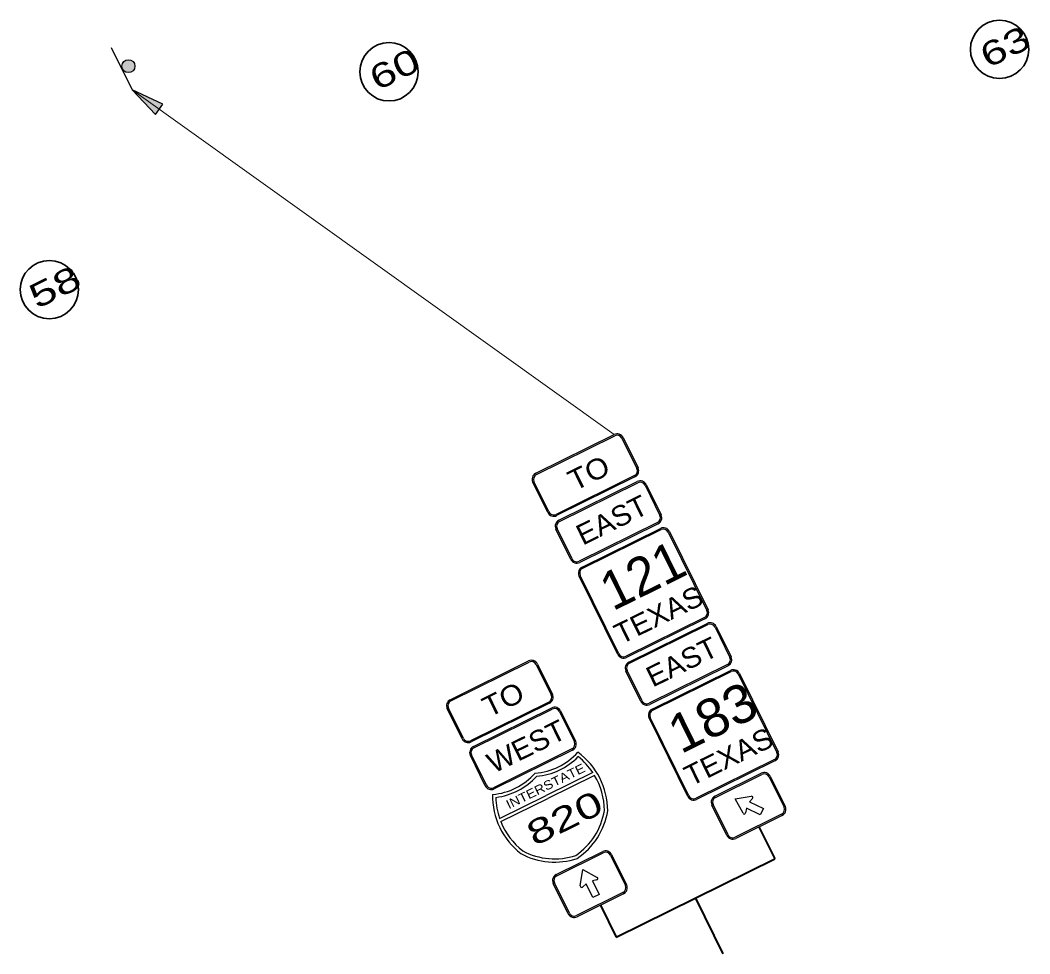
# Model space of a CAD drawing. Extents: x 2356431 to 2371438, y 6972864 to 6982525.
# Drawn here: x 2368952 to 2369535, y 6980523 to 6981061 of the extents above; entities that cross this region are included whole.
import ezdxf
from ezdxf.enums import TextEntityAlignment as Align

# ---------------------------------------------------------------- set-up
doc = ezdxf.new("R2010")
doc.units = 0
doc.header["$LTSCALE"] = 5.6
for name, color, linetype, lineweight in [('1', 7, 'Continuous', 25), ('17', 7, 'Continuous', 35), ('48', 7, 'Continuous', 25)]:
    doc.layers.add(name, color=color, linetype=linetype, lineweight=lineweight)

msp = doc.modelspace()

# ---------------------------------------------------------------- hatches: boundary and pattern name
at = {"layer": '1'}
for points in [[(2369018.675, 6981034.348, 1), (2369011.298, 6981035.483, 1)], [(2369017.082, 6981021.194), (2369030.573, 6981007.07), (2369034.778, 6981012.9)]]:
    msp.add_hatch(color=256, dxfattribs=at).paths.add_polyline_path(points)

# ---------------------------------------------------------------- linework, layer by layer
for p, q in [((2369005.01, 6981045.758), (2369017.082, 6981021.194)), ((2369283.079, 6980627.366), (2369256.179, 6980614.089)), ((2369284.087, 6980625.752), (2369257.018, 6980612.396)), ((2369229.279, 6980600.811), (2369256.179, 6980614.089)), ((2369229.929, 6980599.02), (2369257.018, 6980612.396))]:
    msp.add_line(p, q, dxfattribs=at)
at = {"layer": '1', "lineweight": 13}
msp.add_line((2369017.082, 6981021.194), (2369295.383, 6980822.354), dxfattribs=at)
at = {"layer": '1'}
msp.add_lwpolyline([(2369017.082, 6981021.194), (2369030.573, 6981007.07), (2369034.778, 6981012.9)], close=True, dxfattribs=at)
msp.add_circle((2369014.987, 6981034.916), 3.732, dxfattribs=at)
for centre, radius, start, end in [((2369247.586, 6980663.009), 35.984, 273.44817, 318.29849), ((2369249.694, 6980605.201), 41.954, 0.13097, 53.83335), ((2369247.586, 6980663.009), 37.874, 274.64609, 315.64292), ((2369249.694, 6980605.201), 40.064, 33.57742, 51.44217), ((2369222.557, 6980650.656), 35.984, 274.23709, 319.0874), ((2369222.557, 6980650.656), 37.874, 276.89265, 317.88949), ((2369249.694, 6980605.201), 40.064, 0.34751, 30.85949), ((2369267.159, 6980613.82), 41.954, 178.70222, 232.4046), ((2369267.159, 6980613.82), 40.064, 181.0934, 198.95816), ((2369251.454, 6980611.68), 38.808, 304.10583, 350.75221), ((2369251.454, 6980611.68), 40.698, 303.73968, 350.97558), ((2369267.159, 6980613.82), 40.064, 201.67608, 232.18806), ((2369260.946, 6980616.365), 40.698, 241.55999, 288.79589), ((2369260.946, 6980616.365), 38.808, 241.78337, 288.42975)]:
    msp.add_arc(centre, radius, start, end, dxfattribs=at)
at = {"layer": '17'}
for centre in [(2369517.875, 6981044.608), (2369165.406, 6981031.668), (2368969.308, 6980905.983)]:
    msp.add_circle(centre, 16.828, dxfattribs=at)
at = {"layer": '48'}
for p, q in [((2369250.148, 6980800.029), (2369295.383, 6980822.354)), ((2369250.488, 6980799.34), (2369295.723, 6980821.665)), ((2369299.837, 6980820.27), (2369308.473, 6980802.771)), ((2369300.526, 6980820.61), (2369309.162, 6980803.111)), ((2369307.078, 6980798.657), (2369261.843, 6980776.332)), ((2369307.418, 6980797.968), (2369262.183, 6980775.643)), ((2369263.511, 6980772.953), (2369308.746, 6980795.278)), ((2369257.04, 6980777.387), (2369248.404, 6980794.886)), ((2369257.729, 6980777.727), (2369249.093, 6980795.226)), ((2369263.851, 6980772.264), (2369309.086, 6980794.589)), ((2369313.2, 6980793.194), (2369321.836, 6980775.696)), ((2369313.889, 6980793.534), (2369322.525, 6980776.036)), ((2369270.403, 6980750.312), (2369261.767, 6980767.81)), ((2369271.091, 6980750.652), (2369262.455, 6980768.15)), ((2369320.441, 6980771.581), (2369275.206, 6980749.256)), ((2369320.781, 6980770.893), (2369275.546, 6980748.568)), ((2369276.873, 6980745.877), (2369322.108, 6980768.202)), ((2369277.213, 6980745.189), (2369322.448, 6980767.514)), ((2369326.563, 6980766.119), (2369348.888, 6980720.884)), ((2369327.251, 6980766.458), (2369349.576, 6980721.223)), ((2369297.454, 6980695.5), (2369275.129, 6980740.735)), ((2369298.143, 6980695.839), (2369275.818, 6980741.074)), ((2369347.492, 6980716.769), (2369302.257, 6980694.444)), ((2369347.832, 6980716.081), (2369302.597, 6980693.756)), ((2369303.925, 6980691.065), (2369349.16, 6980713.39)), ((2369304.265, 6980690.377), (2369349.5, 6980712.702)), ((2369353.614, 6980711.306), (2369362.25, 6980693.808)), ((2369354.303, 6980711.646), (2369362.939, 6980694.148)), ((2369200.744, 6980669.396), (2369245.979, 6980691.721)), ((2369201.084, 6980668.708), (2369246.319, 6980691.033)), ((2369250.434, 6980689.638), (2369259.07, 6980672.139)), ((2369251.122, 6980689.977), (2369259.758, 6980672.479)), ((2369310.817, 6980668.424), (2369302.181, 6980685.922)), ((2369311.506, 6980668.764), (2369302.87, 6980686.262)), ((2369360.855, 6980689.694), (2369315.62, 6980667.369)), ((2369361.195, 6980689.005), (2369315.96, 6980666.68)), ((2369317.288, 6980663.99), (2369362.523, 6980686.315)), ((2369317.628, 6980663.301), (2369362.863, 6980685.626)), ((2369367.666, 6980684.571), (2369389.991, 6980639.336)), ((2369366.977, 6980684.231), (2369389.302, 6980638.996)), ((2369257.674, 6980668.025), (2369212.439, 6980645.7)), ((2369258.014, 6980667.336), (2369212.779, 6980645.011)), ((2369207.636, 6980646.755), (2369199, 6980664.254)), ((2369208.325, 6980647.095), (2369199.689, 6980664.593)), ((2369214.107, 6980642.321), (2369259.342, 6980664.646)), ((2369214.447, 6980641.632), (2369259.682, 6980663.957)), ((2369263.796, 6980662.562), (2369272.432, 6980645.064)), ((2369264.485, 6980662.902), (2369273.121, 6980645.403)), ((2369337.869, 6980613.612), (2369315.544, 6980658.847)), ((2369338.557, 6980613.952), (2369316.232, 6980659.187)), ((2369271.037, 6980640.949), (2369225.802, 6980618.624)), ((2369271.377, 6980640.261), (2369226.142, 6980617.936)), ((2369220.999, 6980619.68), (2369212.363, 6980637.178)), ((2369221.688, 6980620.019), (2369213.052, 6980637.518)), ((2369387.907, 6980634.881), (2369342.672, 6980612.556)), ((2369388.247, 6980634.193), (2369343.012, 6980611.868)), ((2369353.557, 6980613.727), (2369380.357, 6980626.953)), ((2369353.897, 6980613.038), (2369380.696, 6980626.265)), ((2369384.811, 6980624.869), (2369393.447, 6980607.371)), ((2369385.499, 6980625.209), (2369394.136, 6980607.711)), ((2369361.138, 6980591.425), (2369352.502, 6980608.924)), ((2369360.449, 6980591.086), (2369351.813, 6980608.584)), ((2369392.052, 6980603.257), (2369365.252, 6980590.03)), ((2369392.392, 6980602.568), (2369365.592, 6980589.342)), ((2369261.986, 6980568.534), (2369288.786, 6980581.76)), ((2369262.326, 6980567.845), (2369289.126, 6980581.071)), ((2369293.24, 6980579.676), (2369301.876, 6980562.178)), ((2369293.929, 6980580.016), (2369302.565, 6980562.518)), ((2369268.879, 6980545.892), (2369260.242, 6980563.391)), ((2369269.567, 6980546.232), (2369260.931, 6980563.731)), ((2369300.481, 6980558.063), (2369273.682, 6980544.837)), ((2369300.821, 6980557.375), (2369274.021, 6980544.148))]:
    msp.add_line(p, q, dxfattribs=at)
at = {"layer": '48', "lineweight": 40}
for p, q in [((2369378.992, 6980595.955), (2369388.092, 6980577.516)), ((2369296.521, 6980532.323), (2369388.092, 6980577.516)), ((2369287.421, 6980550.762), (2369296.521, 6980532.323)), ((2369342.307, 6980554.919), (2369358.166, 6980522.786))]:
    msp.add_line(p, q, dxfattribs=at)
at = {"layer": '48'}
for points in [[(2369369.811, 6980603.839), (2369365.233, 6980612.196), (2369374.569, 6980613.656)], [(2369375.274, 6980612.4), (2369373.599, 6980610.441), (2369381.538, 6980606.529), (2369379.75, 6980602.9), (2369371.813, 6980606.814), (2369371.25, 6980604.043)], [(2369275.854, 6980561.997), (2369277.309, 6980571.414), (2369285.605, 6980566.89)], [(2369285.4, 6980565.464), (2369282.878, 6980564.929), (2369286.796, 6980556.993), (2369283.168, 6980555.202), (2369279.253, 6980563.139), (2369277.119, 6980561.283)]]:
    msp.add_lwpolyline(points, dxfattribs=at)
for centre, radius, start, end in [((2369297.082, 6980818.91), 3.84, 26.26788, 116.26788), ((2369297.082, 6980818.91), 3.072, 26.26788, 116.26788), ((2369305.719, 6980801.412), 3.072, 296.26788, 26.26788), ((2369305.719, 6980801.412), 3.84, 296.26788, 26.26788), ((2369251.847, 6980796.585), 3.84, 116.26788, 206.26788), ((2369251.847, 6980796.585), 3.072, 116.26788, 206.26788), ((2369310.445, 6980791.835), 3.84, 26.26788, 116.26788), ((2369310.445, 6980791.835), 3.072, 26.26788, 116.26788), ((2369260.483, 6980779.087), 3.84, 206.26788, 296.26788), ((2369260.483, 6980779.087), 3.072, 206.26788, 296.26788), ((2369265.21, 6980769.51), 3.84, 116.26788, 206.26788), ((2369265.21, 6980769.51), 3.072, 116.26788, 206.26788), ((2369319.081, 6980774.336), 3.072, 296.26788, 26.26788), ((2369319.081, 6980774.336), 3.84, 296.26788, 26.26788), ((2369323.808, 6980764.759), 3.84, 26.26788, 116.26788), ((2369323.808, 6980764.759), 3.072, 26.26788, 116.26788), ((2369273.846, 6980752.011), 3.84, 206.26788, 296.26788), ((2369273.846, 6980752.011), 3.072, 206.26788, 296.26788), ((2369278.573, 6980742.434), 3.84, 116.26788, 206.26788), ((2369278.573, 6980742.434), 3.072, 116.26788, 206.26788), ((2369346.133, 6980719.524), 3.072, 296.26788, 26.26788), ((2369346.133, 6980719.524), 3.84, 296.26788, 26.26788), ((2369350.859, 6980709.947), 3.84, 26.26788, 116.26788), ((2369350.859, 6980709.947), 3.072, 26.26788, 116.26788), ((2369247.679, 6980688.278), 3.84, 26.26788, 116.26788), ((2369247.679, 6980688.278), 3.072, 26.26788, 116.26788), ((2369300.898, 6980697.199), 3.84, 206.26788, 296.26788), ((2369300.898, 6980697.199), 3.072, 206.26788, 296.26788), ((2369305.624, 6980687.622), 3.84, 116.26788, 206.26788), ((2369305.624, 6980687.622), 3.072, 116.26788, 206.26788), ((2369359.496, 6980692.448), 3.072, 296.26788, 26.26788), ((2369359.496, 6980692.448), 3.84, 296.26788, 26.26788), ((2369364.222, 6980682.871), 3.84, 26.26788, 116.26788), ((2369364.222, 6980682.871), 3.072, 26.26788, 116.26788), ((2369202.444, 6980665.953), 3.84, 116.26788, 206.26788), ((2369202.444, 6980665.953), 3.072, 116.26788, 206.26788), ((2369256.315, 6980670.78), 3.072, 296.26788, 26.26788), ((2369256.315, 6980670.78), 3.84, 296.26788, 26.26788), ((2369314.26, 6980670.123), 3.84, 206.26788, 296.26788), ((2369314.26, 6980670.123), 3.072, 206.26788, 296.26788), ((2369261.042, 6980661.202), 3.84, 26.26788, 116.26788), ((2369261.042, 6980661.202), 3.072, 26.26788, 116.26788), ((2369318.987, 6980660.546), 3.84, 116.26788, 206.26788), ((2369318.987, 6980660.546), 3.072, 116.26788, 206.26788), ((2369211.08, 6980648.455), 3.84, 206.26788, 296.26788), ((2369211.08, 6980648.455), 3.072, 206.26788, 296.26788), ((2369269.678, 6980643.704), 3.072, 296.26788, 26.26788), ((2369269.678, 6980643.704), 3.84, 296.26788, 26.26788), ((2369215.806, 6980638.877), 3.84, 116.26788, 206.26788), ((2369215.806, 6980638.877), 3.072, 116.26788, 206.26788), ((2369386.547, 6980637.636), 3.072, 296.26788, 26.26788), ((2369386.547, 6980637.636), 3.84, 296.26788, 26.26788), ((2369382.056, 6980623.51), 3.84, 26.26788, 116.26788), ((2369382.056, 6980623.51), 3.072, 26.26788, 116.26788), ((2369224.443, 6980621.379), 3.84, 206.26788, 296.26788), ((2369224.443, 6980621.379), 3.072, 206.26788, 296.26788), ((2369341.312, 6980615.311), 3.84, 206.26788, 296.26788), ((2369341.312, 6980615.311), 3.072, 206.26788, 296.26788), ((2369355.257, 6980610.283), 3.84, 116.26788, 206.26788), ((2369355.257, 6980610.283), 3.072, 116.26788, 206.26788), ((2369374.688, 6980612.896), 0.767, 319.26236, 98.90097), ((2369370.488, 6980604.199), 0.767, 208.74934, 348.47791), ((2369390.692, 6980606.011), 3.072, 296.26788, 26.26788), ((2369390.692, 6980606.011), 3.84, 296.26788, 26.26788), ((2369363.893, 6980592.785), 3.072, 206.26788, 296.26788), ((2369363.893, 6980592.785), 3.84, 206.26788, 296.26788), ((2369290.485, 6980578.317), 3.84, 26.26788, 116.26788), ((2369290.485, 6980578.317), 3.072, 26.26788, 116.26788), ((2369263.686, 6980565.09), 3.84, 116.26788, 206.26788), ((2369263.686, 6980565.09), 3.072, 116.26788, 206.26788), ((2369285.237, 6980566.214), 0.767, 281.76638, 61.40499), ((2369299.121, 6980560.818), 3.072, 296.26788, 26.26788), ((2369299.121, 6980560.818), 3.84, 296.26788, 26.26788), ((2369276.611, 6980561.871), 0.767, 171.25336, 310.98193), ((2369272.322, 6980547.592), 3.84, 206.26788, 296.26788), ((2369272.322, 6980547.592), 3.072, 206.26788, 296.26788)]:
    msp.add_arc(centre, radius, start, end, dxfattribs=at)

# ---------------------------------------------------------------- texts
at = {"layer": '1'}
for s, height, width, p in [('INTERSTATE', 5.198, 1.15, (2369234.593, 6980606.135)), ('820', 14.18, 1.45, (2369249.388, 6980584.6))]:
    msp.add_text(s, height=height, rotation=26.268, dxfattribs=dict(at, width=width)).set_placement(p)
at = {"layer": '17'}
for s, width, p in [('63', 1.4, (2369524.17, 6981039.909)), ('60', 1.4, (2369171.651, 6981026.943)), ('58', 1.45, (2368975.602, 6980901.283))]:
    msp.add_text(s, height=14, rotation=26.268, dxfattribs=dict(at, width=width)).set_placement(p, align=Align.CENTER)
at = {"layer": '48'}
for s, height, width, p in [('TO', 11.82, 1.1, (2369283.326, 6980794.867)), ('EAST', 11.82, 1.05, (2369296.689, 6980767.793)), ('TEXAS', 11.82, 1.05, (2369323.691, 6980713.081)), ('EAST', 11.82, 1.05, (2369337.102, 6980685.905)), ('TO', 11.82, 1.1, (2369233.923, 6980664.237)), ('183', 22.16, 1.05, (2369357.119, 6980649.307)), ('WEST', 11.82, 1.05, (2369247.287, 6980637.16)), ('TEXAS', 11.82, 1.05, (2369364.104, 6980631.195))]:
    msp.add_text(s, height=height, rotation=26.188, dxfattribs=dict(at, width=width)).set_placement(p, align=Align.CENTER)
msp.add_text('121', height=22.16, rotation=26.188, dxfattribs=at).set_placement((2369316.704, 6980731.193), align=Align.CENTER)

doc.saveas('drawing.dxf')
